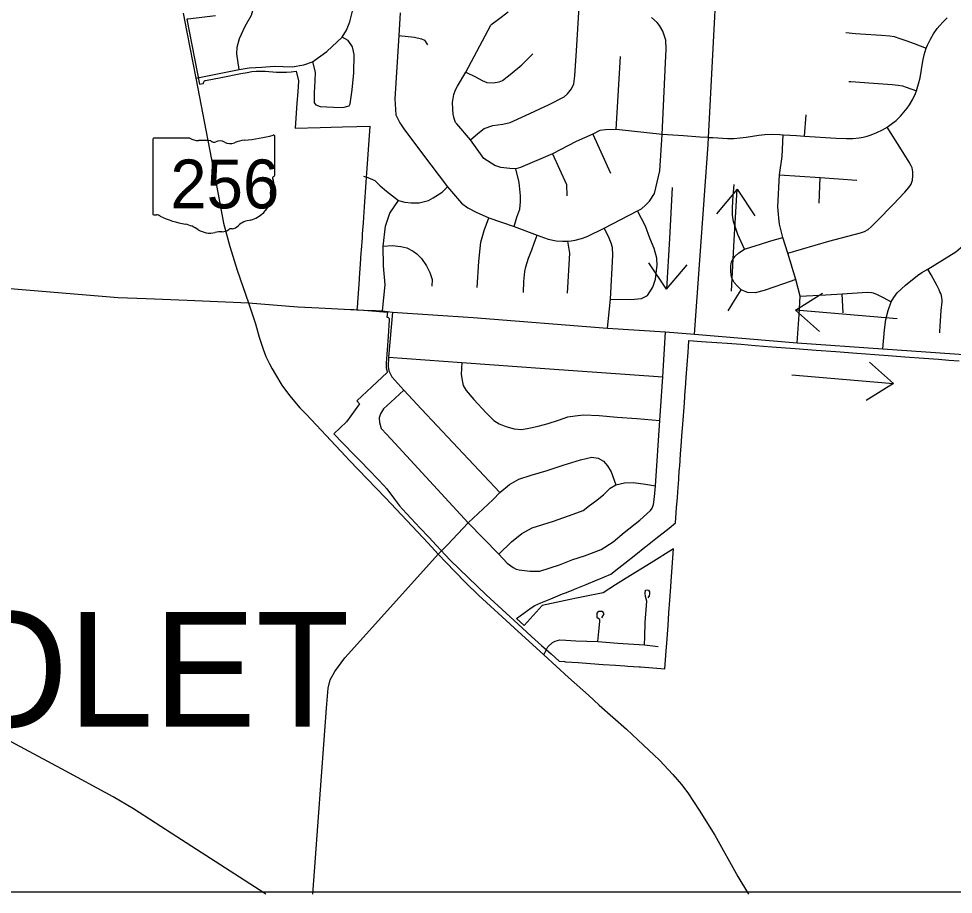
# Model space of a CAD drawing. Extents: x 1880545 to 1948545, y 79309 to 723051.
# Drawn here: x 1888580 to 1895907, y 691136 to 698000 of the extents above; entities that cross this region are included whole.
import ezdxf

# ---------------------------------------------------------------- set-up
doc = ezdxf.new("R2010")
doc.units = 0
for name, color, linetype in [('GM_X_Corporation', 7, 'Continuous'), ('GM_X_County_Road', 7, 'Continuous'), ('GM_X_Rail_Line', 7, 'Continuous'), ('GM_X_State_Location', 7, 'Continuous'), ('GM_X_State_Route', 7, 'Continuous'), ('GM_X_State_Shield', 7, 'Continuous'), ('GM_X_Township_Road', 7, 'Continuous'), ('GM_X_Township_Text', 7, 'Continuous'), ('SH_Text', 7, 'Continuous')]:
    doc.layers.add(name, color=color, linetype=linetype)

msp = doc.modelspace()

# ---------------------------------------------------------------- linework, layer by layer
at = {"layer": 'GM_X_Corporation'}
msp.add_lwpolyline([(1890124, 698023.3), (1889929.9, 697998.8), (1889910, 697996.3), (1889898.4, 697994.8), (1889997.7, 697486.3), (1890010, 697488.6), (1890029.6, 697492.5), (1890029.3, 697495.9), (1890029.5, 697499.4), (1890030.4, 697502.8), (1890031.8, 697506), (1890033.7, 697508.8), (1890036.2, 697511.3), (1890039, 697513.4), (1890042.1, 697514.9), (1890045.5, 697515.9), (1890167.5, 697539.6), (1890320.4, 697569.2), (1890371.7, 697579.1), (1890406.6, 697584.7), (1890441.8, 697588), (1890477.1, 697589), (1890512.4, 697587.6), (1890602.5, 697581.3), (1890640.6, 697579.8), (1890678.8, 697580.6), (1890716.8, 697583.9), (1890754.6, 697589.6), (1890773.9, 697512.1), (1890767.6, 697425.4), (1890761.5, 697338.6), (1890747.7, 697142.8), (1890944, 697147.7), (1891031, 697149.8), (1891118, 697152), (1891230.2, 697154.8), (1891332.7, 697156.6), (1891317.1, 696935.5), (1891307, 696790.9), (1891301.9, 696717.8), (1891288.5, 696526.1), (1891279.5, 696398.4), (1891273.5, 696313.6), (1891271.5, 696284.2), (1891264.5, 696184.4), (1891263, 696163.9), (1891256.9, 696075.7), (1891249.4, 695968.9), (1891248.4, 695954.4), (1891243.5, 695886.1), (1891235.5, 695771.4), (1891235, 695764.9), (1891231.1, 695717.9), (1891285.6, 695713.9), (1891470.1, 695700.6), (1891467.2, 695660.8), (1891470.7, 695660.2), (1891473.9, 695659), (1891477, 695657.3), (1891479.7, 695655.1), (1891481.9, 695652.5), (1891483.7, 695649.5), (1891485, 695646.2), (1891485.7, 695642.8), (1891485.7, 695639.4), (1891476.3, 695508.4), (1891461.3, 695300.2), (1891460.7, 695281.8), (1891461.9, 695263.4), (1891464.9, 695245.2), (1891469.6, 695227.4), (1891349.5, 695114.7), (1891230.6, 695003.5), (1891251.1, 694981.6), (1891150.3, 694839.5), (1891049.9, 694745.7), (1891119.1, 694674.6), (1891146.1, 694647), (1891189, 694603), (1891258.7, 694531.4), (1891328.6, 694459.8), (1891398.4, 694388.1), (1891443.7, 694341.6), (1891465.1, 694313.6), (1891526.1, 694233.7), (1891565.6, 694181.8), (1891589.6, 694156.1), (1891657.9, 694083.1), (1891726.1, 694010), (1891794.4, 693936.9), (1891855.7, 693871.1), (1891924, 693798), (1891965.4, 693753.7), (1892245.7, 693482.8), (1892526.2, 693225.1), (1892600.5, 693158.3), (1892679.4, 693087.4), (1892753.9, 693020.6), (1892817.5, 692963.2), (1892859.5, 692960.2), (1892867.6, 692959.6), (1892965.4, 692952.8), (1893063.1, 692945.9), (1893160.9, 692938.9), (1893258.6, 692932), (1893332.1, 692926.8), (1893356.4, 692925.1), (1893445.1, 692918.8), (1893454.1, 692918.1), (1893551.9, 692911), (1893645.9, 692904.1), (1893656.1, 693043.8), (1893660.5, 693103.6), (1893670.7, 693243.6), (1893678, 693343.4), (1893685.2, 693443.1), (1893692.7, 693545.9), (1893696, 693591.1), (1893714.6, 693845.1), (1893538.9, 693735.8), (1893343.4, 693614.1), (1893258.5, 693561.2), (1893160.9, 693500.4), (1892951.9, 693456.4), (1892903, 693446.1), (1892683.4, 693399.8), (1892543.6, 693244.3), (1892483, 693298.9), (1892596.7, 693380.6), (1892625.2, 693400.9), (1892673.5, 693420.7), (1892751.1, 693452.4), (1892843.9, 693490.3), (1892874.9, 693502.9), (1892932.5, 693526.4), (1892936.6, 693528.1), (1893029.2, 693565.9), (1893115.4, 693601.1), (1893122, 693603.8), (1893222.6, 693644.9), (1893285.1, 693694.5), (1893332.1, 693731.8), (1893418.4, 693800.2), (1893489.5, 693856.7), (1893496.6, 693862.3), (1893575, 693924.5), (1893679.2, 694007.1), (1893729.5, 694047.1), (1893738.2, 694166.4), (1893744.1, 694246.2), (1893747.2, 694289.3), (1893750, 694326), (1893754.6, 694389), (1893756, 694408.9), (1893761.2, 694479.7), (1893761.9, 694488.7), (1893769.2, 694588.4), (1893773.6, 694648.2), (1893776.6, 694688.2), (1893782.4, 694764), (1893784.1, 694787.9), (1893791.5, 694887.6), (1893798.7, 694987.4), (1893806.1, 695087.1), (1893807.1, 695101.1), (1893813.5, 695186.8), (1893820.7, 695286.6), (1893828.1, 695386.3), (1893831.1, 695428.1), (1893834.7, 695477.9), (1893933.5, 695470.6), (1894053.1, 695461.6), (1894134.1, 695455.5), (1894243.9, 695447.3), (1894353.1, 695438.2), (1894483.1, 695428.4), (1894667.5, 695414.6), (1894832.1, 695402.3), (1894986, 695390.7), (1895151.2, 695378.3), (1895290.7, 695367.8), (1895430.5, 695357.3), (1895527.2, 695350), (1895674.6, 695338.9), (1895792, 695330.1), (1895871.7, 695324.1), (1895951.6, 695318.1)], dxfattribs=at)
at = {"layer": 'GM_X_County_Road'}
for p, q in [((1889578.7, 695806.3), (1889899.9, 695793.2)), ((1889899.9, 695793.2), (1890381.7, 695773.6)), ((1890932.2, 695732.9), (1890982.1, 695730.5)), ((1890982.1, 695730.5), (1891181.8, 695720.8)), ((1891408.3, 695710.3), (1891433.4, 695709.1))]:
    msp.add_line(p, q, dxfattribs=at)
for points in [[(1887444.7, 695974.1), (1889359.2, 695815.2), (1889578.7, 695806.3)], [(1890381.7, 695773.6), (1890767.4, 695740.9), (1890932.2, 695732.9)], [(1891181.8, 695720.8), (1891206.8, 695719.6), (1891282.4, 695716.1)], [(1891282.4, 695716.1), (1891378.2, 695711.7), (1891408.3, 695710.3)], [(1891433.4, 695709.1), (1891510, 695699.6), (1892143.6, 695657.5), (1893197.1, 695572.6), (1893650.8, 695545), (1893877.7, 695527.3), (1894682.6, 695459.8), (1895354.4, 695411.8), (1897002.4, 695296.4), (1897771.3, 695231.2), (1898071.9, 695214.6), (1898365.4, 695190.9), (1898485, 695184.9), (1898619.1, 695176.2), (1898815.4, 695159), (1899090.3, 695133.9), (1900081.2, 695057.8), (1900102.5, 695056.2)]]:
    msp.add_lwpolyline(points, dxfattribs=at)
at = {"layer": 'GM_X_Rail_Line'}
msp.add_lwpolyline([(1890518.9, 691136.3), (1890465, 691171), (1889820.2, 691586.4), (1889479.2, 691806.5), (1889321.1, 691900.5), (1888916.1, 692119.6), (1886568.5, 693377.6), (1885720.8, 693829.1)], dxfattribs=at)
at = {"layer": 'GM_X_State_Route'}
for points in [[(1889870.6, 698041.8), (1889897.7, 697895.3), (1889968, 697532.7), (1890142.7, 696623.8), (1890186, 696396.5), (1890208, 696310.4), (1890235.5, 696213.2), (1890293.2, 696028.2), (1890381.7, 695773.6), (1890436, 695608.5), (1890465.8, 695504.2), (1890497.7, 695409.4), (1890518, 695351.9), (1890545.7, 695294.3), (1890567, 695256), (1890593.6, 695210.2), (1890642.6, 695128.2), (1890702.2, 695045.1), (1890785.3, 694948.2), (1890807.7, 694925.8)], [(1890807.7, 694925.8), (1890837.5, 694896), (1891142.1, 694571.2), (1891171.7, 694540.4)], [(1891171.7, 694540.4), (1891456.3, 694244.2), (1891790.7, 693887.4), (1891869.5, 693803.3)], [(1891869.5, 693803.3), (1891995.7, 693669.6), (1892085.7, 693577.5), (1892183.7, 693480.6), (1892465.5, 693224.5)], [(1892465.5, 693224.5), (1892697.1, 693014.1), (1892890.9, 692836.9), (1893046.3, 692696.6)], [(1893046.3, 692696.6), (1893131.8, 692619.4), (1893343.8, 692429.8), (1893477.6, 692306), (1893604.2, 692189), (1893708.5, 692076.2), (1893776.6, 691995.9), (1893825.6, 691931.2), (1893914.9, 691796.2), (1894036.5, 691598.7), (1894218.3, 691275.3), (1894300.1, 691136.3)]]:
    msp.add_lwpolyline(points, dxfattribs=at)
at = {"layer": 'GM_X_State_Shield'}
for p, q in [((1890588.1, 696773.5), (1890588.1, 697077.5)), ((1889631, 697053.1), (1889631, 696472)), ((1889920.7, 697063.1), (1889640.4, 697063.1)), ((1890588, 696773.6), (1890588.1, 696773.5))]:
    msp.add_line(p, q, dxfattribs=at)
for centre, major_axis, start_param, end_param in [((1890247.2, 697855.4), (1015, 0), 4.814394, 5.042369), ((1890577.5, 697078.8), (10.7, 0), 6.141152, 7.989035), ((1889642, 697054.4), (11.1, 0), 1.712693, 3.28349), ((1889987.5, 697130.6), (107.5, 0), 4.042523, 4.731795), ((1890023.1, 696736.9), (386.1, 0), 1.404758, 1.657858), ((1890110.8, 697057.4), (31, 0), 3.836095, 5.185415), ((1890156.3, 696990.2), (64.5, 0), 0.950623, 2.079405), ((1890239.6, 697082.3), (77.6, 0), 4.081561, 5.145723), ((1890376.7, 696885.6), (204.2, 0), 1.699011, 2.107814), ((1890576.8, 696772.4), (11.4, 0), 5.05454, 6.418171), ((1890585.7, 696751.2), (16.5, 0), 1.883978, 3.671073), ((1890480.8, 696712.8), (99, 0), 5.934695, 6.695948), ((1890304.1, 696607.6), (253.9, 0), 5.101752, 6.440018), ((1890626.3, 696646.3), (72, 0), 2.387724, 3.262537), ((1889642.1, 696470.7), (11.2, 0), 3.00124, 4.508301), ((1889643.8, 696530.2), (85.4, 0), 4.665946, 4.897461), ((1889661.2, 696438.5), (30.8, 0), 0.519207, 1.627899), ((1890049.9, 696960.6), (733, 0), 4.195997, 4.488961), ((1890411.1, 696308.8), (139, 0), 1.647645, 2.488434), ((1889831.3, 696210.9), (229.3, 0), 0.823519, 1.323587), ((1890079.4, 696435.6), (145.5, 0), 4.026481, 4.996735), ((1890174.1, 696392.1), (77.5, 0), 4.691044, 5.507374), ((1890244.2, 696335.8), (21.8, 0), 1.147584, 2.315152), ((1890234.9, 696415.7), (82, 0), 4.937069, 5.64225), ((1890163.5, 696234.6), (119.6, 0), 1.495662, 1.94098)]:
    msp.add_ellipse(centre, major_axis=major_axis, ratio=0.8, start_param=start_param, end_param=end_param, dxfattribs=at)
at = {"layer": 'GM_X_Township_Road'}
for p, q in [((1893263.7, 697130.2), (1893298.9, 697703.3)), ((1894741.4, 697079.2), (1894753.2, 697246.5)), ((1893079.9, 697095), (1893220.2, 696787.8)), ((1894854.6, 696554.2), (1894862.4, 696753.8)), ((1895043.8, 695694.6), (1895035, 695841.9)), ((1891165, 693021.6), (1891869.5, 693803.3)), ((1890887, 691136.3), (1890994.2, 692594.6))]:
    msp.add_line(p, q, dxfattribs=at)
for points in [[(1893877.7, 695527.3), (1893984.5, 697013.8), (1893988, 697069.3), (1894056.5, 698365.9), (1894084.6, 698766.4), (1894125, 699405), (1894154.8, 700011.9), (1894198.1, 700583.6), (1894255.6, 701555.1), (1894282.3, 701969.7), (1894290.1, 702131.5), (1894337.5, 702466), (1894370.9, 702994.9), (1894386.8, 703208.7), (1894398.1, 703430.9), (1894398.5, 703471.9), (1894394.6, 703524.9)], [(1890307.3, 697600.3), (1890289.3, 697724.8), (1890292.4, 697777.6), (1890311.9, 697843.2), (1890356.2, 697940.6), (1890405.8, 698027.4), (1890423.5, 698089.8), (1890425.2, 698223.6), (1890439.4, 698259), (1890454.5, 698283.8), (1890486.3, 698319.2), (1890544.7, 698361.7)], [(1889968, 697532.7), (1890152.2, 697570.7), (1890307.3, 697600.3), (1890386.7, 697613.8), (1890487.1, 697618.4), (1890582.2, 697628.7), (1890723.9, 697621.5), (1890815.1, 697638.3), (1890882.3, 697662.4), (1890995.2, 697741.6), (1891115.2, 697854.5), (1891150.7, 697909.9), (1891175.9, 697974.1), (1891205.7, 698088.7), (1891217.2, 698219.4), (1891218.7, 698240.3)], [(1892121.9, 697049.3), (1892179, 697100.1), (1892229.7, 697138.2), (1892297.4, 697161.5), (1892375.7, 697172.1), (1892432.8, 697185), (1892552.1, 697239.7), (1892737.8, 697327.7), (1892855.1, 697388.4), (1892882.5, 697411.8), (1892913.8, 697450.9), (1892931.4, 697488.1), (1892939.2, 697552.6), (1892952.9, 697748.2), (1892974.4, 698092.5), (1892982.2, 698280.2)], [(1891569.4, 698046.2), (1891559.4, 697866.8), (1891529.3, 697370.9), (1891536.4, 697246.6), (1891567.4, 697183.9), (1891600.5, 697137.5), (1891744.9, 696939.1), (1891941.7, 696681.9), (1892051.5, 696554.5), (1892100.1, 696517), (1892165.3, 696482.3), (1892265.8, 696439.2), (1892464.6, 696369.9), (1892645.4, 696301.9), (1892729.8, 696271.1), (1892794.9, 696259.4), (1892844.3, 696255.7), (1892886.3, 696256.5), (1892910.5, 696258.7), (1892941.3, 696264.4), (1892990.9, 696277.2), (1893035.8, 696292.5), (1893169.9, 696357.4), (1893432, 696493.3), (1893461.4, 696510.1), (1893495, 696537.7), (1893526.5, 696569.3), (1893564, 696630.5), (1893605.4, 696805.9), (1893623.5, 697092.7), (1893651.7, 697654.4), (1893656.6, 697759.5), (1893654.2, 697830.4), (1893629.7, 697901.3), (1893602.9, 697945.3), (1893585.7, 697969.8), (1893541.8, 698008.9)], [(1892417.2, 698051.4), (1892340.9, 697994.2), (1892281.8, 697949.5)], [(1893988, 697069.3), (1893920.2, 697072.1), (1893791.4, 697082.3), (1893623.5, 697092.7), (1893263.7, 697130.2), (1893179.9, 697129.7), (1893134.7, 697124.3), (1893079.9, 697095), (1892950.9, 697038.3), (1892764.9, 696939.3), (1892515.3, 696833.4), (1892477.3, 696822.9), (1892430.7, 696825), (1892360.9, 696833.4), (1892312.3, 696848.3), (1892227.6, 696903.3), (1892121.9, 697049.3), (1892014, 697176.3), (1892004.9, 697186.8), (1891996.8, 697208.2), (1891990.3, 697228.5), (1891987.1, 697251.9), (1891982.7, 697289.8), (1891982.2, 697342.4), (1891986.2, 697374.8), (1891991.5, 697405.5), (1892005.5, 697443.3), (1892019.9, 697471.9), (1892085.4, 697581.1), (1892281.8, 697949.5)], [(1893988, 697069.3), (1894022.9, 697067.4), (1894137.6, 697061.1), (1894186.5, 697061.1), (1894235.2, 697064.7), (1894283.7, 697071.4), (1894381.2, 697087), (1894430.4, 697092.2), (1894479.9, 697094.1), (1894545.8, 697092), (1894573.2, 697090.2), (1894677.1, 697083.1), (1894741.4, 697079.2), (1894988.5, 697064.3), (1895070.3, 697060.7), (1895119.1, 697061.7), (1895167.7, 697066.7), (1895199.8, 697072.1), (1895231.4, 697079.6), (1895262.4, 697089.3), (1895307.9, 697107.2), (1895351.7, 697128.7), (1895387.4, 697149.8), (1895420.7, 697172), (1895458.8, 697202.5), (1895494.2, 697236.1), (1895546.4, 697298.5), (1895564.4, 697325.5), (1895588.4, 697368.1), (1895609.4, 697412.3), (1895617.4, 697433.3), (1895635.3, 697489.3), (1895646, 697537.1), (1895667.2, 697666.7), (1895677.9, 697715.1), (1895694.7, 697767.6), (1895705.1, 697793.4), (1895727.1, 697837.9), (1895752.4, 697880.6), (1895780.5, 697921.5), (1895801.3, 697947.4), (1895823.6, 697971.8), (1895859.3, 698006.2)], [(1895065.4, 697892.6), (1895140.4, 697883.6), (1895180.4, 697881.4), (1895345, 697870.4), (1895410.3, 697865.4), (1895442.1, 697858.8), (1895488.8, 697844.5), (1895535.3, 697827.9), (1895599.6, 697803.9), (1895694.7, 697767.6)], [(1890882.3, 697662.4), (1890904, 697580.7), (1890901.5, 697513.4), (1890896.7, 697417.3), (1890896.7, 697340.5), (1890908.8, 697323.7), (1890942.3, 697311.7), (1891048, 697306.8), (1891120, 697304.4), (1891170.5, 697316.5), (1891180, 697333.3), (1891194.4, 697441.4), (1891206.5, 697575.9), (1891211.3, 697720), (1891196.9, 697780), (1891163.2, 697828.1), (1891115.2, 697854.5)], [(1891559.4, 697866.8), (1891682.6, 697853.8), (1891738, 697841.4), (1891761.1, 697830.7), (1891785.7, 697794.5)], [(1892085.4, 697581.1), (1892161.8, 697544.2), (1892214.1, 697514.1), (1892249.4, 697500.1), (1892299.6, 697497.1), (1892345.6, 697505.1), (1892373.3, 697516.1), (1892434.2, 697563.2), (1892524, 697638.4), (1892611.6, 697724.6)], [(1895086.9, 697506.5), (1895103.4, 697506.2), (1895281.7, 697494.6), (1895427.5, 697484.5), (1895475.8, 697479.3), (1895507.6, 697473), (1895538.6, 697463.5), (1895617.4, 697433.3)], [(1894610.7, 696161.6), (1894931.8, 696255.7), (1895178.7, 696321.4), (1895209.5, 696332.5), (1895238.5, 696347.6), (1895264.2, 696367.9), (1895309.7, 696415.1), (1895435.3, 696544.5), (1895526.5, 696638.6), (1895558.8, 696675.6), (1895575.9, 696703.6), (1895586.5, 696734.5), (1895590.6, 696767), (1895590, 696799.8), (1895587.5, 696815.9), (1895583.1, 696831.6), (1895576.8, 696846.7), (1895560.8, 696875.3), (1895499.5, 696972.3), (1895387.4, 697149.8)], [(1894682.6, 695459.8), (1894698.6, 695678.4), (1894705.3, 695825.4), (1894671.2, 695956.3), (1894610.7, 696161.6), (1894570.9, 696284.8), (1894544.8, 696389.3), (1894539.8, 696435.4), (1894537.4, 696466.4), (1894531.7, 696525.8), (1894544.6, 696774.9), (1894564.4, 696919.8), (1894573.2, 697090.2)], [(1892764.9, 696939.3), (1892873.8, 696701.2), (1892878.4, 696611.5)], [(1892464.6, 696369.9), (1892485.7, 696444.4), (1892508.9, 696507.9), (1892515.1, 696565.1), (1892515.1, 696609.9), (1892504.3, 696715.1), (1892477.3, 696822.9)], [(1894544.6, 696774.9), (1894862.4, 696753.8), (1895150.4, 696734.7)], [(1891283.5, 696764.2), (1891316.8, 696755.9), (1891370.9, 696730.5), (1891415, 696690.7), (1891464.7, 696647.7), (1891557.4, 696575.8), (1891606, 696561.5), (1891656.8, 696556), (1891720.8, 696557.1), (1891791.5, 696574.8), (1891830.1, 696595.7), (1891900.8, 696641), (1891941.7, 696681.9)], [(1894270, 696192.7), (1894216.5, 696308.5), (1894183, 696409.2), (1894175, 696459.5), (1894176.2, 696507.7), (1894178.6, 696577.6), (1894188, 696700.6)], [(1891433.4, 695709.1), (1891452.3, 695913.8), (1891440.3, 696061.7), (1891436.3, 696217.9), (1891455.3, 696372.1), (1891488.5, 696474.1), (1891557.4, 696575.8)], [(1893218.8, 695801.6), (1893379.4, 695798.8), (1893462.4, 695805.2), (1893510.2, 695829.1), (1893551.7, 695894.6), (1893572.5, 695958.5), (1893584.6, 696067.7), (1893582, 696121.3), (1893561.3, 696199.5), (1893527.8, 696279.3), (1893492.7, 696373.5), (1893432, 696493.3)], [(1892173.8, 695892.5), (1892187.4, 696097.1), (1892196.7, 696199.1), (1892204, 696246.9), (1892228.6, 696340.1), (1892265.8, 696439.2)], [(1893197.1, 695572.6), (1893218.8, 695801.6), (1893237.7, 696147), (1893234, 696206), (1893224.8, 696239.1), (1893203.7, 696291.6), (1893169.9, 696357.4)], [(1892538.6, 695853.3), (1892541.1, 695938.4), (1892548.6, 696017.7), (1892556.5, 696055.1), (1892575.5, 696123), (1892603.5, 696188.6), (1892621.2, 696241.1), (1892645.4, 696301.9)], [(1894671.2, 695956.3), (1894574.5, 695922.2), (1894425, 695869.4), (1894353.3, 695851.9), (1894293.6, 695854.4), (1894243.9, 695875.5), (1894211.6, 695906.6), (1894189.2, 695932.7), (1894169.3, 695973.8), (1894163.1, 696014.8), (1894163.1, 696063.4), (1894169.3, 696094.5), (1894178, 696111.9), (1894195.4, 696135.5), (1894226.5, 696165.4), (1894270, 696192.7), (1894328.5, 696210.2), (1894388.1, 696228.8), (1894477.7, 696257.4), (1894570.9, 696284.8)], [(1891436.3, 696217.9), (1891507.6, 696221.8), (1891574.8, 696215), (1891622.3, 696202.4), (1891671.9, 696176.2), (1891700.8, 696155.9), (1891737, 696120), (1891777.3, 696061.9), (1891804.1, 696009.6), (1891822.7, 695954.3), (1891819.6, 695902)], [(1892883, 695847.3), (1892900.3, 696160.7), (1892886.3, 696256.5)], [(1895354.4, 695411.8), (1895367.7, 695561.1), (1895378.4, 695641.1), (1895397.1, 695713.1), (1895420.7, 695779.3), (1895439.4, 695814.4), (1895466.4, 695851.8), (1895533.1, 695910.6), (1895625.1, 695987.8), (1895659.5, 696009.4), (1895708.5, 696036.3), (1895872.9, 696137.4), (1895926.3, 696172.5), (1895962.7, 696204.8), (1896020.2, 696249.7)], [(1895800.2, 695536.8), (1895801.3, 695548.2), (1895806.9, 695630.8), (1895813, 695713.5), (1895818.3, 695779.6), (1895818.6, 695796.1), (1895817.3, 695812.6), (1895814, 695828.7), (1895808.9, 695844.5), (1895802.5, 695859.8), (1895795.5, 695874.8), (1895780.4, 695904.4), (1895732.8, 695991.7), (1895708.5, 696036.3)], [(1894143.2, 695710.1), (1894191.7, 695789.7), (1894243.9, 695875.5)], [(1894705.3, 695825.4), (1894906.5, 695835.8), (1895035, 695841.9), (1895232.8, 695856.2), (1895264.7, 695852.9), (1895279, 695849.6), (1895309.7, 695838.6), (1895358.1, 695815), (1895420.7, 695779.3)], [(1891510, 695699.6), (1891478.6, 695345.3), (1891477.2, 695274.1), (1891482.4, 695240.2), (1891504.5, 695193.5), (1891599.4, 695086.9), (1891738.4, 694938.6), (1892352.8, 694285.3)], [(1891599.4, 695086.9), (1891496.7, 694994.5), (1891440.8, 694942.5), (1891416.2, 694902.3), (1891406.2, 694869.9), (1891407.9, 694835.7), (1891422.5, 694788.4), (1891466.5, 694739.5), (1891561, 694638.4), (1892102.8, 694047.6), (1892344.5, 693801.6), (1892409.2, 693731.9), (1892456, 693697.5), (1892478.9, 693686), (1892504.6, 693680.3), (1892587.7, 693667.9), (1892665, 693669.8), (1892818.7, 693719.5), (1892923.7, 693759.6), (1893016.3, 693790.1), (1893145.2, 693837.9), (1893240.6, 693900), (1893327.1, 693972.9), (1893448.4, 694070.2), (1893532.6, 694145.5), (1893546.6, 694163.5), (1893555.7, 694191.6), (1893564.7, 694252.8), (1893571.8, 694337.4), (1893606.2, 694849.2), (1893629.7, 695193.3), (1893650.8, 695545)], [(1891478.6, 695345.3), (1892054.2, 695304), (1892704.7, 695257.4), (1893629.7, 695193.3)], [(1892054.2, 695304), (1892049, 695210.4), (1892058.1, 695151.9), (1892064.6, 695124.6), (1892088, 695084.3), (1892147.8, 695015.3), (1892243.9, 694911.3), (1892305.3, 694851.4), (1892348, 694823.6), (1892399.3, 694802.2), (1892465.5, 694785.1), (1892525.3, 694780.8), (1892593.7, 694791.5), (1892653.5, 694806.5), (1892730.4, 694827.9), (1892811.6, 694853.5), (1892886.3, 694879.2), (1892941.9, 694885.6), (1893008.1, 694894.1), (1893129.8, 694889.9), (1893270.9, 694877), (1893424.7, 694866.3), (1893606.2, 694849.2)], [(1891869.5, 693803.3), (1891941.4, 693875.7), (1892102.8, 694047.6), (1892300.7, 694231.6), (1892352.8, 694285.3), (1892427.8, 694347.8), (1892500.7, 694389.5), (1892598.7, 694422.8), (1892723.7, 694458.3), (1892848.7, 694500), (1892984.2, 694541.7), (1893073.8, 694562.5), (1893123.8, 694554.2), (1893163.4, 694531.2), (1893196.7, 694493.7), (1893225.9, 694447.9), (1893261.3, 694345.7)], [(1892344.5, 693801.6), (1892444.5, 693899.6), (1892523.7, 693964.2), (1892604.9, 694008), (1892771.6, 694062.2), (1892925.8, 694116.4), (1893005, 694145.6), (1893055, 694183.1), (1893102.9, 694218.5), (1893163.4, 694268.6), (1893217.5, 694318.6), (1893261.3, 694345.7), (1893328, 694361.1), (1893396.2, 694365.1), (1893494.5, 694352.1), (1893571.8, 694337.4)], [(1893486, 693091.5), (1893488.4, 693155.7), (1893491.5, 693266.3), (1893504.3, 693433.8), (1893494.2, 693469.5), (1893490.6, 693496.1), (1893493.3, 693519), (1893506.2, 693523.5), (1893517.1, 693519.9), (1893526.3, 693507), (1893526.3, 693491.5), (1893522.6, 693475.9), (1893511.6, 693459.4)], [(1893119.9, 693117.8), (1893128.4, 693196.1), (1893132.7, 693246.3), (1893137, 693280.3), (1893135, 693290.4), (1893115, 693302.6), (1893115.3, 693338.7), (1893127.4, 693354.7), (1893155.4, 693354.6), (1893167.3, 693334.4), (1893149.1, 693304.4)], [(1892697.1, 693014.1), (1892727, 693075.6), (1892763.6, 693109.1), (1892785.4, 693119.4), (1892821.4, 693129.7), (1892870.6, 693129.2), (1892948.5, 693124.3), (1893119.9, 693117.8), (1893277.1, 693104.8), (1893486, 693091.5), (1893593.6, 693077.8)], [(1890994.2, 692594.6), (1891005.8, 692752.3), (1891020.7, 692817.8), (1891059.4, 692883.3), (1891136.8, 692990.4), (1891165, 693021.6)]]:
    msp.add_lwpolyline(points, dxfattribs=at)
at = {"layer": 'SH_Text'}
for p, q in [((1893704.1, 696677.4), (1893681.6, 696278)), ((1894211.3, 696662.5), (1894050.5, 696471.1)), ((1894189.2, 696263.1), (1894211.3, 696662.5)), ((1894211.3, 696662.5), (1894350, 696454.6)), ((1893681.6, 696278), (1893659.2, 695878.6)), ((1894167.2, 695863.7), (1894189.2, 696263.1)), ((1893659.2, 695878.6), (1893520.7, 696086.7)), ((1893659.2, 695878.6), (1893820.2, 696069.9)), ((1894670.4, 695715.3), (1894882.4, 695847.7)), ((1894670.4, 695715.3), (1894856.8, 695548.8)), ((1895068.9, 695681.2), (1894670.4, 695715.3)), ((1895467.4, 695647.1), (1895068.9, 695681.2)), ((1895437.2, 695139.8), (1895250.9, 695306.5)), ((1894640.2, 695208.9), (1895038.7, 695174.3)), ((1895038.7, 695174.3), (1895437.2, 695139.8)), ((1895437.2, 695139.8), (1895225, 695007.6))]:
    msp.add_line(p, q, dxfattribs=at)
msp.add_lwpolyline([(1884489.7, 720381.4), (1928140.8, 720381.4), (1928140.8, 691152), (1884489.7, 691152)], close=True, dxfattribs=at)

# ---------------------------------------------------------------- texts
at = {"layer": 'GM_X_State_Location'}
for s, p in [('s', (1890135.7, 696354.4)), ('r', (1890135.6, 696354.4))]:
    msp.add_text(s, height=1, dxfattribs=at).set_placement(p)
at = {"layer": 'GM_X_State_Shield'}
msp.add_text('256', height=382.85, dxfattribs=at).set_placement((1889768.7, 696513))
at = {"layer": 'GM_X_Township_Text'}
msp.add_text('VIOLET', height=900, rotation=0.00001, dxfattribs=at).set_placement((1886893.6, 692449.8))

doc.saveas('drawing.dxf')
